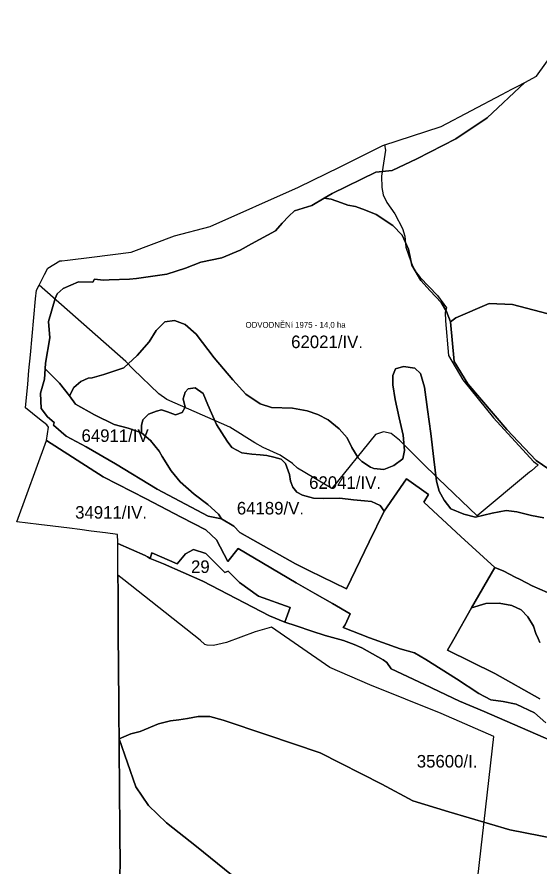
# Model space of a CAD drawing. Extents: x -521621 to -516761, y -1190184 to -1184927.
# Drawn here: x -520810 to -520185, y -1187011 to -1185996 of the extents above; entities that cross this region are included whole.
import ezdxf

# ---------------------------------------------------------------- set-up
doc = ezdxf.new("R2010")
doc.units = 0
doc.layers.add('BPEJ_s', color=7, linetype='Continuous')
doc.layers.add('odvodneni_s', color=7, linetype='Continuous')

msp = doc.modelspace()

# ---------------------------------------------------------------- linework, layer by layer
at = {"layer": 'BPEJ_s'}
for p, q in [((-520202.5, -1186073.7), (-520247.3, -1186115.9)), ((-520211, -1186078.2), (-520202.5, -1186073.7)), ((-520202.5, -1186073.7), (-520202.5, -1186073.7)), ((-520229.9, -1186088.2), (-520217.8, -1186081.8)), ((-520217.8, -1186081.8), (-520211, -1186078.2)), ((-520302.4, -1186126.2), (-520229.9, -1186088.2)), ((-520247.3, -1186115.9), (-520284.9, -1186141.1)), ((-520372, -1186149.1), (-520302.4, -1186126.2)), ((-520284.9, -1186141.1), (-520331.4, -1186164.8)), ((-520423.1, -1186174.4), (-520372, -1186149.1)), ((-520331.4, -1186164.8), (-520361.2, -1186178.9)), ((-520473, -1186199), (-520423.1, -1186174.4)), ((-520380.4, -1186181.1), (-520432.6, -1186206.5)), ((-520361.2, -1186178.9), (-520380.4, -1186181.1)), ((-520578.8, -1186245.7), (-520473, -1186199)), ((-520432.6, -1186206.5), (-520442.2, -1186212.1)), ((-520442.2, -1186212.1), (-520457.1, -1186220.8)), ((-520477.9, -1186227.1), (-520484.6, -1186233.5)), ((-520457.1, -1186220.8), (-520477.9, -1186227.1)), ((-520484.6, -1186233.5), (-520492.5, -1186242)), ((-520621.2, -1186257.1), (-520578.8, -1186245.7)), ((-520492.5, -1186242), (-520500.4, -1186251)), ((-520673, -1186276.5), (-520621.2, -1186257.1)), ((-520500.4, -1186251), (-520529.1, -1186266.6)), ((-520529.1, -1186266.6), (-520542.6, -1186274.2)), ((-520720.2, -1186282.3), (-520673, -1186276.5)), ((-520542.6, -1186274.2), (-520564.6, -1186283.3)), ((-520763.6, -1186290.1), (-520758.4, -1186287)), ((-520758.4, -1186287), (-520755.8, -1186286.7)), ((-520755.8, -1186286.7), (-520749.2, -1186285.9)), ((-520749.2, -1186285.9), (-520720.2, -1186282.3)), ((-520589.6, -1186288.6), (-520608, -1186295.4)), ((-520564.6, -1186283.3), (-520589.6, -1186288.6)), ((-520776.5, -1186303), (-520772.5, -1186295.5)), ((-520772.5, -1186295.5), (-520763.6, -1186290.1)), ((-520608, -1186295.4), (-520630.4, -1186302.6)), ((-520783.2, -1186315.7), (-520776.5, -1186303)), ((-520716.7, -1186308.8), (-520719, -1186312.2)), ((-520706, -1186309.9), (-520716.7, -1186308.8)), ((-520674.9, -1186308.6), (-520699.3, -1186309.7)), ((-520666.7, -1186307.8), (-520674.9, -1186308.6)), ((-520630.4, -1186302.6), (-520666.7, -1186307.8)), ((-520786.4, -1186321.7), (-520783.2, -1186315.7)), ((-520736.2, -1186312), (-520754.2, -1186319.8)), ((-520719, -1186312.2), (-520736.2, -1186312)), ((-520699.3, -1186309.7), (-520706, -1186309.9)), ((-520787.4, -1186332.3), (-520786.4, -1186321.7)), ((-520761.4, -1186326.4), (-520763.9, -1186332)), ((-520754.2, -1186319.8), (-520761.4, -1186326.4)), ((-520793.5, -1186399), (-520787.4, -1186332.3)), ((-520763.9, -1186332), (-520772, -1186359.4)), ((-520772, -1186359.4), (-520770.3, -1186378.9)), ((-520770.3, -1186378.9), (-520775.6, -1186408.9)), ((-520795.2, -1186418), (-520793.5, -1186399)), ((-520775.6, -1186408.9), (-520776, -1186415.8)), ((-520796.7, -1186434.3), (-520795.2, -1186418)), ((-520776, -1186415.8), (-520776.8, -1186428.1)), ((-520776.8, -1186428.1), (-520781.3, -1186444.9)), ((-520799.3, -1186462.3), (-520796.7, -1186434.3)), ((-520781.3, -1186444.9), (-520780.6, -1186463.3)), ((-520782.5, -1186476), (-520799.3, -1186462.3)), ((-520780.6, -1186463.3), (-520773, -1186473)), ((-520774, -1186482.8), (-520782.5, -1186476)), ((-520773, -1186473), (-520765, -1186479.8)), ((-520765, -1186479.8), (-520765.8, -1186483)), ((-520774.1, -1186501.4), (-520771.7, -1186485.7)), ((-520771.7, -1186485.7), (-520774, -1186482.8)), ((-520765.8, -1186483), (-520750.6, -1186496.1)), ((-520706.4, -1186544.9), (-520774.1, -1186501.4)), ((-520750.6, -1186496.1), (-520726.8, -1186509.1)), ((-520726.8, -1186509.1), (-520691.6, -1186529.2)), ((-520691.6, -1186529.2), (-520641.9, -1186559.5)), ((-520655.1, -1186571.2), (-520706.4, -1186544.9)), ((-520370.4, -1186585.8), (-520343.9, -1186547.4)), ((-520343.9, -1186547.4), (-520317.5, -1186566.1)), ((-520641.9, -1186559.5), (-520581.1, -1186591.8)), ((-520613.2, -1186593.1), (-520655.1, -1186571.2)), ((-520317.5, -1186566.1), (-520321.8, -1186573.2)), ((-520321.8, -1186573.2), (-520323, -1186575)), ((-520323, -1186575), (-520279, -1186616)), ((-520583.6, -1186608.3), (-520613.2, -1186593.1)), ((-520581.1, -1186591.8), (-520565.2, -1186595.2)), ((-520388.4, -1186622.5), (-520370.4, -1186585.8)), ((-520565.2, -1186595.2), (-520550.5, -1186603.8)), ((-520570.9, -1186620.1), (-520583.6, -1186608.3)), ((-520550.5, -1186603.8), (-520543.3, -1186611.4)), ((-520543.3, -1186611.4), (-520527.5, -1186620)), ((-520557.6, -1186646), (-520570.9, -1186620.1)), ((-520527.5, -1186620), (-520476.6, -1186648.6)), ((-520415.8, -1186678.8), (-520388.4, -1186622.5)), ((-520279, -1186616), (-520238.4, -1186653.1)), ((-520545.2, -1186630.6), (-520557.6, -1186646)), ((-520475.7, -1186671.4), (-520545.2, -1186630.6)), ((-520476.6, -1186648.6), (-520459.9, -1186657.2)), ((-520238.4, -1186653.1), (-520266, -1186701.3)), ((-520459.9, -1186657.2), (-520415.8, -1186678.8)), ((-520453.5, -1186684.2), (-520475.7, -1186671.4)), ((-520432.5, -1186696.1), (-520453.5, -1186684.2)), ((-520411.3, -1186708.5), (-520432.5, -1186696.1)), ((-520266, -1186701.3), (-520287.4, -1186738.6)), ((-520417.1, -1186721.5), (-520411.3, -1186708.5)), ((-520419.7, -1186724.7), (-520417.1, -1186721.5)), ((-520388.1, -1186737.2), (-520419.7, -1186724.7)), ((-520351.5, -1186750.2), (-520388.1, -1186737.2)), ((-520287.4, -1186738.6), (-520295, -1186751.8)), ((-520334.2, -1186755.2), (-520351.5, -1186750.2)), ((-520320.6, -1186763.1), (-520334.2, -1186755.2)), ((-520295, -1186751.8), (-520238.4, -1186779.9)), ((-520284, -1186786.1), (-520320.6, -1186763.1)), ((-520257.5, -1186803.6), (-520284, -1186786.1)), ((-520238.4, -1186779.9), (-520184.6, -1186810)), ((-520243.2, -1186811.3), (-520257.5, -1186803.6)), ((-520228.3, -1186813.2), (-520243.2, -1186811.3)), ((-520212.6, -1186816.3), (-520228.3, -1186813.2)), ((-520190.8, -1186826.8), (-520212.6, -1186816.3)), ((-520177.2, -1186838.5), (-520190.8, -1186826.8)), ((-520687.2, -1186880.5), (-520687.4, -1186857.7)), ((-520687.4, -1186857.7), (-520687.4, -1186857.7)), ((-520687.4, -1186857.7), (-520667.5, -1186915)), ((-520687, -1186905.8), (-520687.2, -1186880.5)), ((-520686.9, -1186929.2), (-520687, -1186905.8)), ((-520667.5, -1186915), (-520652.4, -1186937.6)), ((-520686.7, -1186955.5), (-520686.9, -1186929.2)), ((-520652.4, -1186937.6), (-520630.9, -1186958.1)), ((-520686.5, -1186978.4), (-520686.7, -1186955.5)), ((-520630.9, -1186958.1), (-520594.8, -1186986.3)), ((-520686.3, -1187000.3), (-520686.5, -1186978.4)), ((-520594.8, -1186986.3), (-520544.7, -1187027.1)), ((-520686.3, -1187010.2), (-520686.3, -1187000.3)), ((-520687.1, -1187022.9), (-520686.3, -1187010.2))]:
    msp.add_line(p, q, dxfattribs=at)
for points in [[(-520166.8, -1186352.1), (-520217.3, -1186338.9), (-520245.2, -1186337.7), (-520285, -1186354.9), (-520291.4, -1186359.7), (-520296.1, -1186347.3), (-520302.5, -1186336.6), (-520315.7, -1186322.8), (-520326.8, -1186310.3), (-520337.4, -1186292.2), (-520341.6, -1186272.9), (-520348.9, -1186256.3), (-520360.1, -1186244.6), (-520380.2, -1186231.6), (-520392.8, -1186226.5), (-520404.9, -1186222.1), (-520414.1, -1186220.4), (-520421.6, -1186217.5), (-520433.9, -1186213), (-520442.2, -1186212.1), (-520432.6, -1186206.5), (-520380.4, -1186181.1), (-520361.2, -1186178.9), (-520331.4, -1186164.8), (-520284.9, -1186141.1), (-520247.3, -1186115.9), (-520202.5, -1186073.7), (-520188.5, -1186066.3), (-520137.8, -1185995.6)], [(-520179.6, -1186593.7), (-520194.5, -1186591.1), (-520212.1, -1186586.8), (-520224.9, -1186585.2), (-520241.4, -1186588.4), (-520261.6, -1186593.2), (-520275.5, -1186589.5), (-520290.9, -1186583.1), (-520298.9, -1186572.9), (-520304.8, -1186561.8), (-520308, -1186550), (-520311.2, -1186523.9), (-520314.9, -1186493), (-520318.6, -1186464.3), (-520322.3, -1186437.6), (-520327.1, -1186421.6), (-520334, -1186415.2), (-520347.4, -1186413.1), (-520356.9, -1186415.8), (-520360.1, -1186423.8), (-520360.1, -1186435), (-520357.5, -1186452.5), (-520352.7, -1186474.4), (-520347.9, -1186495.2), (-520346.3, -1186513.3), (-520348.4, -1186523.4), (-520359.1, -1186531.4), (-520370.8, -1186536.2), (-520382.8, -1186534.7), (-520386.8, -1186533.1), (-520397.2, -1186526.6), (-520401.5, -1186522.2), (-520409.3, -1186509.7), (-520415, -1186498.4), (-520424.3, -1186487.5), (-520437.4, -1186476.6), (-520449.9, -1186470.3), (-520462.7, -1186466.2), (-520480.2, -1186462.8), (-520505.2, -1186462.2), (-520519, -1186457.8), (-520536.1, -1186446.2), (-520551.4, -1186429), (-520573.9, -1186402.8), (-520595.5, -1186374.4), (-520608.6, -1186362.8), (-520621.1, -1186358.1), (-520633, -1186359.7), (-520643, -1186370), (-520651.7, -1186383.4), (-520665.8, -1186400), (-520681.7, -1186414.7), (-520705.7, -1186422.8), (-520719.6, -1186426.4), (-520724.6, -1186427.1), (-520733.2, -1186430.9), (-520741.5, -1186438.1), (-520746.6, -1186448.1), (-520758.9, -1186433.1), (-520776, -1186415.8), (-520775.6, -1186408.9), (-520770.3, -1186378.9), (-520772, -1186359.4), (-520763.9, -1186332), (-520761.4, -1186326.4), (-520754.2, -1186319.8), (-520736.2, -1186312), (-520719, -1186312.2), (-520716.7, -1186308.8), (-520706, -1186309.9), (-520699.3, -1186309.7), (-520674.9, -1186308.6), (-520666.7, -1186307.8), (-520630.4, -1186302.6), (-520608, -1186295.4), (-520589.6, -1186288.6), (-520564.6, -1186283.3), (-520542.6, -1186274.2), (-520529.1, -1186266.6), (-520500.4, -1186251), (-520492.5, -1186242), (-520484.6, -1186233.5), (-520477.9, -1186227.1), (-520457.1, -1186220.8), (-520442.2, -1186212.1), (-520433.9, -1186213), (-520421.6, -1186217.5), (-520414.1, -1186220.4), (-520404.9, -1186222.1), (-520392.8, -1186226.5), (-520380.2, -1186231.6), (-520360.1, -1186244.6), (-520348.9, -1186256.3), (-520341.6, -1186272.9), (-520337.4, -1186292.2), (-520326.8, -1186310.3), (-520315.7, -1186322.8), (-520302.5, -1186336.6), (-520296.1, -1186347.3), (-520291.4, -1186359.7), (-520287.1, -1186407.1), (-520270.7, -1186433.8), (-520224.1, -1186488.3), (-520188.8, -1186525.2), (-520166.1, -1186540.8)], [(-520166.1, -1186540.8), (-520188.8, -1186525.2), (-520224.1, -1186488.3), (-520270.7, -1186433.8), (-520287.1, -1186407.1), (-520291.4, -1186359.7), (-520285, -1186354.9), (-520245.2, -1186337.7), (-520217.3, -1186338.9), (-520166.8, -1186352.1)], [(-520175.4, -1186683.2), (-520193.5, -1186675.2), (-520208.2, -1186667.3), (-520214.1, -1186664.5), (-520227.7, -1186657.5), (-520238.4, -1186653.1), (-520279, -1186616), (-520323, -1186575), (-520321.8, -1186573.2), (-520317.5, -1186566.1), (-520343.9, -1186547.4), (-520370.4, -1186585.8), (-520375.4, -1186579.1), (-520385.9, -1186574.4), (-520394, -1186573.4), (-520407.1, -1186572.2), (-520423.4, -1186570.3), (-520443.4, -1186570.9), (-520455.2, -1186570.3), (-520468.4, -1186566.9), (-520474.9, -1186563.1), (-520479.6, -1186557.2), (-520482.7, -1186550), (-520483.7, -1186541.9), (-520488.4, -1186529.1), (-520493.7, -1186523.7), (-520502.4, -1186521.2), (-520510.8, -1186519.4), (-520518.7, -1186518.4), (-520528.6, -1186517.8), (-520540.8, -1186516.2), (-520552.7, -1186509.7), (-520558.3, -1186502.2), (-520571.1, -1186482.5), (-520581.4, -1186459), (-520587.1, -1186445.3), (-520596.7, -1186438.4), (-520604.9, -1186439.7), (-520608.6, -1186443.7), (-520610.8, -1186451.5), (-520608.3, -1186461.6), (-520612, -1186468.1), (-520619.9, -1186470.9), (-520629.5, -1186467.2), (-520636.7, -1186465), (-520642.7, -1186466.6), (-520652.3, -1186470), (-520659.2, -1186476.6), (-520660.8, -1186483.4), (-520660.8, -1186492.2), (-520676.7, -1186486.6), (-520693.2, -1186482.5), (-520717, -1186470.9), (-520739.5, -1186458.1), (-520746.6, -1186448.1), (-520741.5, -1186438.1), (-520733.2, -1186430.9), (-520724.6, -1186427.1), (-520719.6, -1186426.4), (-520705.7, -1186422.8), (-520681.7, -1186414.7), (-520665.8, -1186400), (-520651.7, -1186383.4), (-520643, -1186370), (-520633, -1186359.7), (-520621.1, -1186358.1), (-520608.6, -1186362.8), (-520595.5, -1186374.4), (-520573.9, -1186402.8), (-520551.4, -1186429), (-520536.1, -1186446.2), (-520519, -1186457.8), (-520505.2, -1186462.2), (-520480.2, -1186462.8), (-520462.7, -1186466.2), (-520449.9, -1186470.3), (-520437.4, -1186476.6), (-520424.3, -1186487.5), (-520415, -1186498.4), (-520409.3, -1186509.7), (-520401.5, -1186522.2), (-520397.2, -1186526.6), (-520386.8, -1186533.1), (-520382.8, -1186534.7), (-520370.8, -1186536.2), (-520359.1, -1186531.4), (-520348.4, -1186523.4), (-520346.3, -1186513.3), (-520347.9, -1186495.2), (-520352.7, -1186474.4), (-520357.5, -1186452.5), (-520360.1, -1186435), (-520360.1, -1186423.8), (-520356.9, -1186415.8), (-520347.4, -1186413.1), (-520334, -1186415.2), (-520327.1, -1186421.6), (-520322.3, -1186437.6), (-520318.6, -1186464.3), (-520314.9, -1186493), (-520311.2, -1186523.9), (-520308, -1186550), (-520304.8, -1186561.8), (-520298.9, -1186572.9), (-520290.9, -1186583.1), (-520275.5, -1186589.5), (-520261.6, -1186593.2), (-520241.4, -1186588.4), (-520224.9, -1186585.2), (-520212.1, -1186586.8), (-520194.5, -1186591.1), (-520179.6, -1186593.7)], [(-520171.2, -1186859.6), (-520251, -1186825), (-520280.6, -1186812.8), (-520313.3, -1186797.3), (-520315.7, -1186795.9), (-520362.2, -1186774.2), (-520367.4, -1186766.5), (-520371.7, -1186763.4), (-520397.1, -1186749.1), (-520406.5, -1186745.3), (-520419.4, -1186740.2), (-520441, -1186734.3), (-520457.1, -1186729.2), (-520475.9, -1186722.9), (-520489.4, -1186718.5), (-520482.8, -1186700.9), (-520520.7, -1186687.2), (-520543.5, -1186670.9), (-520556.9, -1186657.6), (-520561.2, -1186659.2), (-520583.7, -1186636.3), (-520598.6, -1186631.8), (-520608.2, -1186636.9), (-520618, -1186648.8), (-520648.3, -1186635.8), (-520650.4, -1186642.2), (-520653.6, -1186640.3), (-520656.5, -1186639), (-520689.1, -1186624.6), (-520689.1, -1186623.8), (-520689.1, -1186623.1), (-520689.1, -1186622.1), (-520689.1, -1186621.2), (-520689.1, -1186619.3), (-520689.2, -1186617.4), (-520689.2, -1186615.5), (-520689.2, -1186613.7), (-520703.8, -1186611.8), (-520720.7, -1186609.6), (-520734.4, -1186607.8), (-520746.6, -1186606.3), (-520766.8, -1186603.7), (-520783.4, -1186601.7), (-520809.6, -1186598.6), (-520774.1, -1186501.4), (-520706.4, -1186544.9), (-520655.1, -1186571.2), (-520613.2, -1186593.1), (-520583.6, -1186608.3), (-520570.9, -1186620.1), (-520557.6, -1186646), (-520545.2, -1186630.6), (-520475.7, -1186671.4), (-520453.5, -1186684.2), (-520432.5, -1186696.1), (-520411.3, -1186708.5), (-520417.1, -1186721.5), (-520419.7, -1186724.7), (-520388.1, -1186737.2), (-520351.5, -1186750.2), (-520334.2, -1186755.2), (-520320.6, -1186763.1), (-520284, -1186786.1), (-520257.5, -1186803.6), (-520243.2, -1186811.3), (-520228.3, -1186813.2), (-520212.6, -1186816.3), (-520190.8, -1186826.8), (-520177.2, -1186838.5)], [(-520689.1, -1186624.6), (-520656.5, -1186639), (-520653.6, -1186640.3), (-520650.4, -1186642.2), (-520634.2, -1186648.6), (-520587.5, -1186669.6), (-520507.8, -1186710.8), (-520489.4, -1186718.5), (-520475.9, -1186722.9), (-520457.1, -1186729.2), (-520441, -1186734.3), (-520419.4, -1186740.2), (-520406.5, -1186745.3), (-520397.1, -1186749.1), (-520371.7, -1186763.4), (-520367.4, -1186766.5), (-520362.2, -1186774.2), (-520315.7, -1186795.9), (-520313.3, -1186797.3), (-520280.6, -1186812.8), (-520251, -1186825), (-520171.2, -1186859.6)], [(-520687.4, -1186857.7), (-520687.4, -1186857.7), (-520687.4, -1186853.1), (-520687.6, -1186835.5), (-520687.6, -1186830.6), (-520687.6, -1186824.5), (-520687.8, -1186807), (-520688, -1186781.6), (-520688.4, -1186722.5), (-520688.4, -1186719.2), (-520688.5, -1186713.1), (-520688.5, -1186707.2), (-520688.5, -1186701.7), (-520688.6, -1186697.3), (-520688.6, -1186692.9), (-520688.6, -1186688.3), (-520688.7, -1186684.7), (-520688.7, -1186680.2), (-520688.7, -1186675.8), (-520688.7, -1186673.6), (-520688.8, -1186671.1), (-520688.8, -1186666.1), (-520688.8, -1186662.3), (-520688.9, -1186657.9), (-520688.9, -1186654.6), (-520688.9, -1186650.8), (-520688.9, -1186646.6), (-520689, -1186642.4), (-520689, -1186640.8), (-520689, -1186638.6), (-520689, -1186631.8), (-520689.1, -1186624.6)], [(-520184.5, -1186742.9), (-520186.3, -1186738.1), (-520189.1, -1186731.8), (-520192.1, -1186723.3), (-520198.8, -1186712.2), (-520206.9, -1186703.7), (-520218.1, -1186698.7), (-520233.3, -1186695.6), (-520249.1, -1186696.1), (-520266, -1186701.3), (-520238.4, -1186653.1), (-520227.7, -1186657.5), (-520214.1, -1186664.5), (-520208.2, -1186667.3), (-520193.5, -1186675.2), (-520175.4, -1186683.2)], [(-520184.6, -1186810), (-520238.4, -1186779.9), (-520295, -1186751.8), (-520287.4, -1186738.6), (-520266, -1186701.3), (-520249.1, -1186696.1), (-520233.3, -1186695.6), (-520218.1, -1186698.7), (-520206.9, -1186703.7), (-520198.8, -1186712.2), (-520192.1, -1186723.3), (-520189.1, -1186731.8), (-520186.3, -1186738.1), (-520184.5, -1186742.9)], [(-520544.7, -1187027.1), (-520594.8, -1186986.3), (-520630.9, -1186958.1), (-520652.4, -1186937.6), (-520667.5, -1186915), (-520687.4, -1186857.7), (-520673.4, -1186852), (-520662.3, -1186849.2), (-520640.3, -1186839.8), (-520626.1, -1186836.2), (-520615.9, -1186835), (-520605.9, -1186833.5), (-520593, -1186831.3), (-520579.1, -1186831.3), (-520563, -1186835.4), (-520511, -1186853), (-520447.3, -1186874.7), (-520373.5, -1186911.8), (-520336.5, -1186932), (-520293.4, -1186945.2), (-520220.4, -1186966.5), (-520147, -1186980.8)], [(-520003.6, -1187012.6), (-520013.7, -1187007.7), (-520063.1, -1186996.9), (-520089.7, -1186990.9), (-520147, -1186980.8), (-520220.4, -1186966.5), (-520293.4, -1186945.2), (-520336.5, -1186932), (-520373.5, -1186911.8), (-520447.3, -1186874.7), (-520511, -1186853), (-520563, -1186835.4), (-520579.1, -1186831.3), (-520593, -1186831.3), (-520605.9, -1186833.5), (-520615.9, -1186835), (-520626.1, -1186836.2), (-520640.3, -1186839.8), (-520662.3, -1186849.2), (-520673.4, -1186852), (-520687.4, -1186857.7)]]:
    msp.add_lwpolyline(points, dxfattribs=at)
for points in [[(-520776, -1186415.8), (-520758.9, -1186433.1), (-520746.6, -1186448.1), (-520739.5, -1186458.1), (-520717, -1186470.9), (-520693.2, -1186482.5), (-520676.7, -1186486.6), (-520660.8, -1186492.2), (-520650.1, -1186501.6), (-520639.5, -1186514.1), (-520636.1, -1186520.6), (-520625.2, -1186537.5), (-520614.5, -1186550.7), (-520597.7, -1186565.5), (-520581.2, -1186577.8), (-520568.5, -1186589.3), (-520565.2, -1186595.2), (-520581.1, -1186591.8), (-520641.9, -1186559.5), (-520691.6, -1186529.2), (-520726.8, -1186509.1), (-520750.6, -1186496.1), (-520765.8, -1186483), (-520765, -1186479.8), (-520773, -1186473), (-520780.6, -1186463.3), (-520781.3, -1186444.9), (-520776.8, -1186428.1)], [(-520660.8, -1186492.2), (-520660.8, -1186483.4), (-520659.2, -1186476.6), (-520652.3, -1186470), (-520642.7, -1186466.6), (-520636.7, -1186465), (-520629.5, -1186467.2), (-520619.9, -1186470.9), (-520612, -1186468.1), (-520608.3, -1186461.6), (-520610.8, -1186451.5), (-520608.6, -1186443.7), (-520604.9, -1186439.7), (-520596.7, -1186438.4), (-520587.1, -1186445.3), (-520581.4, -1186459), (-520571.1, -1186482.5), (-520558.3, -1186502.2), (-520552.7, -1186509.7), (-520540.8, -1186516.2), (-520528.6, -1186517.8), (-520518.7, -1186518.4), (-520510.8, -1186519.4), (-520502.4, -1186521.2), (-520493.7, -1186523.7), (-520488.4, -1186529.1), (-520483.7, -1186541.9), (-520482.7, -1186550), (-520479.6, -1186557.2), (-520474.9, -1186563.1), (-520468.4, -1186566.9), (-520455.2, -1186570.3), (-520443.4, -1186570.9), (-520423.4, -1186570.3), (-520407.1, -1186572.2), (-520394, -1186573.4), (-520385.9, -1186574.4), (-520375.4, -1186579.1), (-520370.4, -1186585.8), (-520388.4, -1186622.5), (-520415.8, -1186678.8), (-520459.9, -1186657.2), (-520476.6, -1186648.6), (-520527.5, -1186620), (-520543.3, -1186611.4), (-520550.5, -1186603.8), (-520565.2, -1186595.2), (-520568.5, -1186589.3), (-520581.2, -1186577.8), (-520597.7, -1186565.5), (-520614.5, -1186550.7), (-520625.2, -1186537.5), (-520636.1, -1186520.6), (-520639.5, -1186514.1), (-520650.1, -1186501.6)], [(-520650.4, -1186642.2), (-520648.3, -1186635.8), (-520618, -1186648.8), (-520608.2, -1186636.9), (-520598.6, -1186631.8), (-520583.7, -1186636.3), (-520561.2, -1186659.2), (-520556.9, -1186657.6), (-520543.5, -1186670.9), (-520520.7, -1186687.2), (-520482.8, -1186700.9), (-520489.4, -1186718.5), (-520507.8, -1186710.8), (-520587.5, -1186669.6), (-520634.2, -1186648.6)]]:
    msp.add_lwpolyline(points, close=True, dxfattribs=at)
at = {"layer": 'odvodneni_s'}
msp.add_lwpolyline([(-520783.2, -1186315.7), (-520776.5, -1186303), (-520772.5, -1186295.5), (-520758.4, -1186287), (-520755.8, -1186286.7), (-520749.2, -1186285.9), (-520720.2, -1186282.3), (-520673, -1186276.5), (-520621.2, -1186257.1), (-520578.8, -1186245.7), (-520473, -1186199), (-520423.1, -1186174.4), (-520372, -1186149.1), (-520370, -1186148.4), (-520369.2, -1186154.5), (-520373.7, -1186185.8), (-520373.5, -1186199.2), (-520371.6, -1186208.1), (-520367.4, -1186217.1), (-520357.9, -1186230.5), (-520348.8, -1186248.4), (-520345.9, -1186257.3), (-520344.8, -1186270.7), (-520338.9, -1186287.6), (-520334.6, -1186297.5), (-520327.4, -1186306.6), (-520306.8, -1186328.4), (-520295.9, -1186342.9), (-520297.6, -1186348.7), (-520297.2, -1186358.5), (-520293.8, -1186399.9), (-520276.5, -1186429.1), (-520239.9, -1186474.4), (-520192.2, -1186526.6), (-520186.4, -1186530.6), (-520194.4, -1186537.7), (-520197, -1186539.1), (-520259.3, -1186591.4), (-520306.2, -1186546.9), (-520326, -1186527.4), (-520352.2, -1186501), (-520362.3, -1186492.9), (-520371.3, -1186491.2), (-520380.8, -1186494.2), (-520433.3, -1186558.6), (-520474.3, -1186534.6), (-520480, -1186528.9), (-520495.1, -1186519.1), (-520515.2, -1186509.9), (-520525.3, -1186504.1), (-520555.2, -1186485.7), (-520630.6, -1186452.3), (-520640.1, -1186445.6), (-520670.6, -1186416.1), (-520679.3, -1186407.2)], close=True, dxfattribs=at)
msp.add_lwpolyline([(-520280, -1187212.1), (-520239.3, -1186854.9), (-520302.6, -1186827.4), (-520387.9, -1186793.3), (-520435.6, -1186772.4), (-520505.2, -1186724.3), (-520525, -1186729.9), (-520559.1, -1186742.6), (-520574.7, -1186746.4), (-520582, -1186746), (-520584.8, -1186745), (-520590.6, -1186740.1), (-520681.8, -1186667.9), (-520688.8, -1186662.3), (-520688.8, -1186666.1), (-520688.8, -1186671.1), (-520688.7, -1186673.6), (-520688.7, -1186675.8), (-520688.7, -1186680.2), (-520688.7, -1186684.7), (-520688.6, -1186688.3), (-520688.6, -1186692.9), (-520688.6, -1186695.6), (-520688.6, -1186697.3), (-520688.5, -1186701.7), (-520688.5, -1186707.2), (-520688.5, -1186713.1), (-520688.4, -1186719.2), (-520688.4, -1186722.5), (-520688, -1186781.6), (-520687.8, -1186807), (-520687.6, -1186824.5), (-520687.6, -1186830.6), (-520687.6, -1186835.5), (-520687.4, -1186853.1), (-520687.2, -1186880.5), (-520687, -1186905.8), (-520686.9, -1186929.2), (-520686.7, -1186955.5), (-520686.5, -1186978.4), (-520686.3, -1187000.3), (-520686.3, -1187010.2), (-520687.1, -1187022.9)], dxfattribs=at)

# ---------------------------------------------------------------- texts
at = {"layer": 'BPEJ_s'}
for s, p in [('62021/IV.', (-520481.8, -1186391.1)), ('64911/IV.', (-520732.4, -1186503.1)), ('62041/IV.', (-520460.3, -1186559.2)), ('34911/IV.', (-520740, -1186594.8)), ('64189/V.', (-520546.7, -1186589.8)), ('29', (-520601.5, -1186659.7)), ('35600/I.', (-520331.6, -1186892.1))]:
    msp.add_text(s, height=15, dxfattribs=at).set_placement(p)
at = {"layer": 'odvodneni_s'}
msp.add_text('ODVODNĚNí 1975 - 14,0 ha', height=7, dxfattribs=at).set_placement((-520536.3, -1186366.8))

doc.saveas('drawing.dxf')
